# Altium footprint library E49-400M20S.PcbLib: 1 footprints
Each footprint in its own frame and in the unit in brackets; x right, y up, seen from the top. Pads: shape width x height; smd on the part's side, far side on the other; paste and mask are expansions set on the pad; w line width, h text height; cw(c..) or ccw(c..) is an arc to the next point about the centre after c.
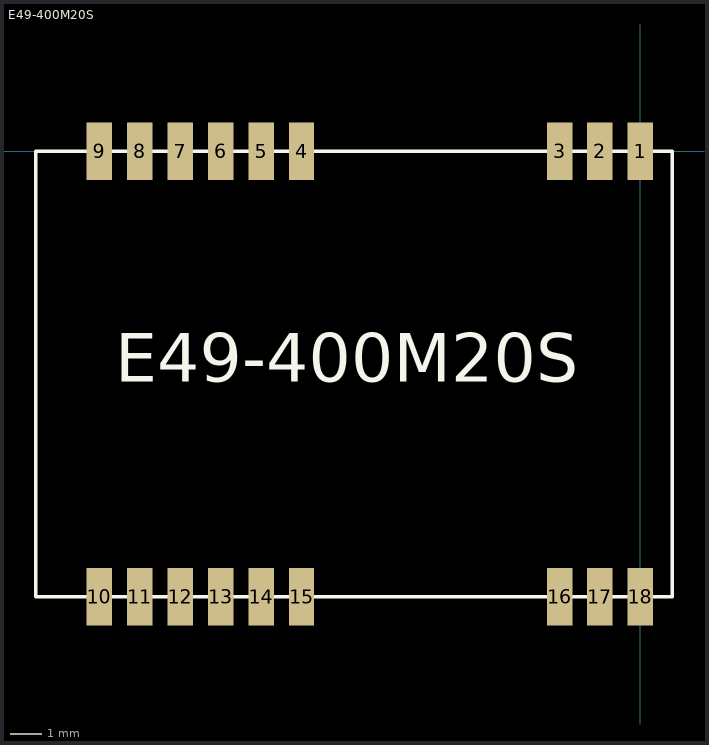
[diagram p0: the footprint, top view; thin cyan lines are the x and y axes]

## E49-400M20S [mm]
pads (18):
  rect 0.8x1.8 smd: 1(0,0) 2(-1.27,0) 3(-2.54,0) 4(-10.65,0) 5(-11.92,0) 6(-13.19,0) 7(-14.46,0) 8(-15.73,0) 9(-17,0) 10(-17,-14) 11(-15.73,-14) 12(-14.46,-14) 13(-13.19,-14) 14(-11.92,-14) 15(-10.65,-14) 16(-2.54,-14) 17(-1.27,-14) 18(0,-14)
Top Overlay:
  lines w0.1: -19,-14 -19,0 1,0 1,-14 -19,-14
  text "E49-400M20S" at -16.51,-7.239 h1.52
